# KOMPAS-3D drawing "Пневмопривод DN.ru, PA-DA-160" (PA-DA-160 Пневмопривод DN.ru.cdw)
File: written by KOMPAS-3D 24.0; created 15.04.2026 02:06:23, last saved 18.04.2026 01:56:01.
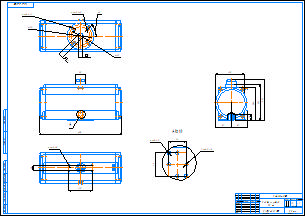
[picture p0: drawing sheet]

Document properties: Автор: DN.ru; Форматы листов документа: A1; Полное имя файла: PA-DA-160 Пневмопривод DN.ru.m3d; Масса: 20; Наименование: Пневмопривод DN.ru; Количество листов документа: 1; Примечание: D290-00299

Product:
- Part/product: Пневмопривод DN.ru  | designation PA-DA-160
    Масса: 20
    Раздел спецификации: Прочие изделия
    Примечание: D290-00299

Views: Вид 1, Вид:1, Проекционный вид 2, Проекционный вид 5, Местный разрез 1, Выносной элемент 6, Выносной элемент А, Выносной элемент
Referenced files in C:\Работа\PA-DA-х Пневмопривод DN.ru\052\: PA-DA-052 Пневмопривод DN.ru.m3d
Referenced files in C:\Работа\PA-DA-х Пневмопривод DN.ru\160\: PA-DA-160 Пневмопривод DN.ru.m3d
Referenced files in C:\Program Files\ASCON\KOMPAS-3D v24\Templates\: Чертеж_DN.ru.cdt
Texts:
  objid
  viewid
  PA-DA-160
  Чертеж_DN.ru.cdt
  Пневмопривод
  Пневмопривод DN.ru
  PA-DA-160 Пневмопривод DN.ru
Dimensions and other numbers on the sheet: 0; 3; 2; 4; 55; 608; 458; 9; 4 отв.; 10; 27; 102; 125; 12; 6; 159; 87; 184; 197; 227; 31; 7; 1; 2 отв.; 24; 32; 5; 1:2; 20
